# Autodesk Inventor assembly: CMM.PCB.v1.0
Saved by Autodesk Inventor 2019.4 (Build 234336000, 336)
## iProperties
Created: 2021-03
Part Number: CMM.PCB.v1.0
Document SubType Name: Assembly
Designer: Administrator
Title: CMM.PCB.v1.0 v2
Author: Administrator
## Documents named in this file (3)
- c:\worker\convert-fusion-r02\tmp\job-1\102\output\files\0328255d-0a6c-475c-bcc0-a427a23ae33c\e845dfa0-be98-444f-bb61-36dcab99285b.iam
- c:\worker\convert-fusion-r02\tmp\job-1\102\output\files\0328255d-0a6c-475c-bcc0-a427a23ae33c\Board.ipt
- c:\worker\convert-fusion-r02\tmp\job-1\102\output\files\0328255d-0a6c-475c-bcc0-a427a23ae33c\Packages.iam
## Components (2 placed, 2 different names)
1. Board:1
2. Packages:1 [sub-assembly]
